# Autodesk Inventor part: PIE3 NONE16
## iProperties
Shininess: 64.0
Length Units: 11269
Angle Units: 11279
Time Units: 11290
Mass Units: 11286
Length Display Precision: 3
Angle Display Precision: 2
Compacted: True
Part Number: PIE3 NONE16
Document SubType Name: Modeling
Created: 2004-08
Designer: John Blackburn
Manufacturer: Standard
Standards Organization: Custom
Density: 0.0
Volumn: 0.0
Area: 0.0
PropertySet Name: Model Information
Control State: 0
Master: False
Checked Out: False
Author: John Blackburn
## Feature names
1. Erst1
